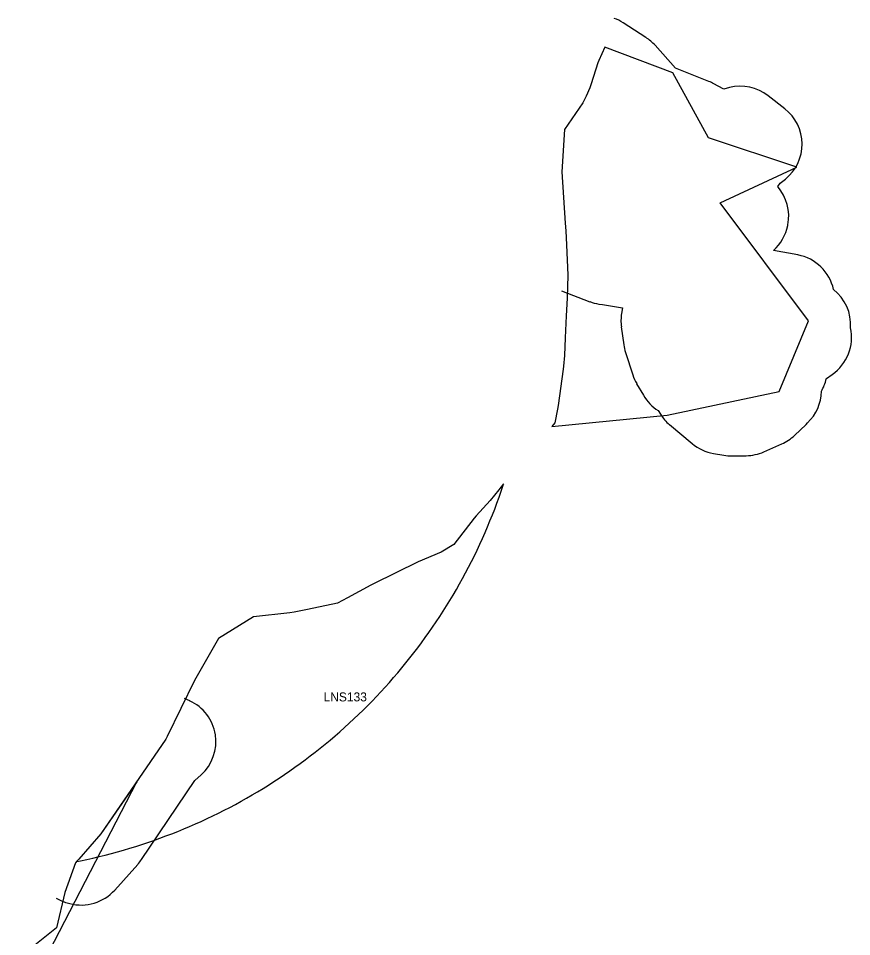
# Model space of a CAD drawing. Extents: x -546762 to -536351, y -1046851 to -1035695.
# Drawn here: x -545178 to -544249, y -1042054 to -1041031 of the extents above; entities that cross this region are included whole.
import ezdxf

# ---------------------------------------------------------------- set-up
doc = ezdxf.new("R2010")
doc.units = 0
for name, color, linetype in [('Vrstva 23', 7, 'Continuous'), ('Vrstva 24', 7, 'Continuous'), ('Vrstva 48', 7, 'Continuous')]:
    doc.layers.add(name, color=color, linetype=linetype)

msp = doc.modelspace()

# ---------------------------------------------------------------- linework, layer by layer
at = {"layer": 'Vrstva 23'}
for points in [[(-544478.4, -1041052.5), (-544503.9, -1041036)], [(-544408.3, -1041101.4), (-544445.4, -1041086.6), (-544468.3, -1041061.1)], [(-544385.3, -1041108.2), (-544391.7, -1041109.8), (-544392.4, -1041109.7), (-544402.8, -1041104)], [(-544323.7, -1041131.7), (-544342.2, -1041117.3)], [(-544331.6, -1041218.5), (-544328.7, -1041214.6), (-544323, -1041210.1)], [(-544320.4, -1041261.9), (-544320.2, -1041261)], [(-544309.2, -1041294.6), (-544336.3, -1041289.6)], [(-544572.6, -1041334.6), (-544540.9, -1041346.7)], [(-544531.1, -1041349.3), (-544526.8, -1041350), (-544504.6, -1041353.5), (-544505.7, -1041359.7)], [(-544505.9, -1041374.8), (-544503.1, -1041394.6)], [(-544501.2, -1041403.1), (-544493.1, -1041428.2)], [(-544277.5, -1041432.6), (-544277.3, -1041432.1), (-544271, -1041427.7)], [(-544488.8, -1041438), (-544481.3, -1041450.9)], [(-544464.9, -1041468), (-544462.3, -1041472)], [(-544452.1, -1041483.6), (-544426.8, -1041504.8)], [(-544312.9, -1041495.6), (-544300, -1041483.3)], [(-544300, -1041483.3), (-544298.2, -1041481.6)], [(-544347, -1041513.9), (-544327.1, -1041505.1)], [(-544403.2, -1041515.7), (-544391.6, -1041517.7)], [(-544382.7, -1041518.4), (-544366.8, -1041518.2)], [(-544987, -1041791.2), (-544992.8, -1041788.6)], [(-545040.7, -1041968.1), (-544981.1, -1041880), (-544974.2, -1041873.7)], [(-545070.5, -1042002), (-545044.9, -1041973.4)], [(-545123.7, -1042016.2), (-545120.6, -1042017)]]:
    msp.add_lwpolyline(points, dxfattribs=at)
for centre, start, end in [((-544531.1, -1041078), 57.1301, 69.7905), ((-544505.5, -1041094.5), 41.9531, 57.1301), ((-544426.8, -1041147.8), 61.2505, 68.1963), ((-544373, -1041156.7), 52.0504, 104.2278), ((-544354.4, -1041171.2), 308.8802, 52.0504), ((-544369.3, -1041251.3), 348.8112, 41.0233), ((-544369.5, -1041252.2), 311.5394, 348.8112), ((-544318.2, -1041343.8), 12.2473, 79.5739), ((-544300.2, -1041372.5), 356.4059, 51.8996), ((-544523.2, -1041299.9), 249.212, 260.8837), ((-544456.3, -1041368), 170.4755, 187.8827), ((-544299.2, -1041386.4), 304.3378, 12.4104), ((-544453.6, -1041387.8), 187.8827, 197.8307), ((-544445.5, -1041412.9), 197.8307, 210.1018), ((-544326.3, -1041421.8), 330.4344, 347.4681), ((-544438, -1041425.8), 210.1018, 237.5143), ((-544332.8, -1041445.4), 313.6678, 358.83), ((-544420.1, -1041445.3), 212.3187, 230.1188), ((-544334.5, -1041447.1), 313.6393, 313.6678), ((-544347.4, -1041459.4), 293.9544, 313.6393), ((-544394.8, -1041466.4), 230.1188, 260.3616), ((-544383.2, -1041468.4), 260.3616, 270.5762), ((-544367.3, -1041468.2), 270.5762, 293.9544), ((-545013.5, -1041834.1), 65.5109, 65.6412), ((-545007.8, -1041836.7), 312.1957, 65.5109), ((-545082.1, -1041940), 318.2032, 325.8942), ((-545107.8, -1041968.7), 255.1271, 318.2032), ((-545110.8, -1041967.9), 239.8285, 255.1271)]:
    msp.add_arc(centre, 50, start, end, dxfattribs=at)
at = {"layer": 'Vrstva 24'}
for points in [[(-544583.3, -1041485.8), (-544454.8, -1041473), (-544330, -1041446.7), (-544297.1, -1041367.9), (-544395.7, -1041236.4), (-544310.3, -1041197), (-544408.8, -1041164.2), (-544448.3, -1041091.9), (-544524.3, -1041063.1), (-544531.1, -1041078), (-544532.2, -1041080.7), (-544539.5, -1041104.2), (-544541.1, -1041108.3), (-544544.9, -1041117.7), (-544548.7, -1041125.2), (-544569.2, -1041154.9), (-544572.1, -1041201.9), (-544568.3, -1041259.2), (-544567.9, -1041267.6), (-544567, -1041283.3), (-544565.4, -1041317), (-544566.4, -1041342.6), (-544567.2, -1041362.6), (-544568.6, -1041387), (-544569.3, -1041406.7), (-544570.3, -1041418.6), (-544570.6, -1041421.8), (-544576.4, -1041462.2), (-544577, -1041466.5), (-544580, -1041481.7), (-544583.3, -1041485.8)], [(-545177.7, -1042136.7), (-545046, -1041881.4), (-545086, -1041939.5), (-545110.5, -1041967.6), (-545110.8, -1041967.9), (-545111.6, -1041968.8), (-545112.7, -1041970), (-545114.1, -1041971.7), (-545126.2, -1042004.6), (-545135.4, -1042044.2), (-545178, -1042078.1)]]:
    msp.add_lwpolyline(points, dxfattribs=at)
at = {"layer": 'Vrstva 48'}
msp.add_lwpolyline([(-545112.8, -1041970.2), (-545108.8, -1041969.4), (-545101.8, -1041967.9), (-545094.9, -1041966.4), (-545088, -1041964.7), (-545081.1, -1041963), (-545074.2, -1041961.3), (-545067.4, -1041959.4), (-545060.6, -1041957.5), (-545053.7, -1041955.5), (-545047, -1041953.4), (-545040.2, -1041951.2), (-545033.5, -1041949), (-545026.8, -1041946.7), (-545020.1, -1041944.3), (-545013.4, -1041941.8), (-545006.8, -1041939.3), (-545000.2, -1041936.7), (-544993.6, -1041934), (-544987.1, -1041931.2), (-544980.6, -1041928.4), (-544974.1, -1041925.5), (-544967.6, -1041922.5), (-544961.2, -1041919.5), (-544954.9, -1041916.4), (-544948.5, -1041913.2), (-544942.2, -1041909.9), (-544936, -1041906.6), (-544929.7, -1041903.2), (-544923.5, -1041899.7), (-544917.4, -1041896.1), (-544911.3, -1041892.5), (-544905.2, -1041888.8), (-544899.2, -1041885.1), (-544893.2, -1041881.3), (-544887.3, -1041877.4), (-544881.4, -1041873.4), (-544875.5, -1041869.4), (-544869.7, -1041865.3), (-544864, -1041861.2), (-544858.3, -1041856.9), (-544852.6, -1041852.7), (-544847, -1041848.3), (-544841.4, -1041843.9), (-544835.9, -1041839.4), (-544830.4, -1041834.9), (-544825, -1041830.3), (-544819.7, -1041825.7), (-544814.4, -1041821), (-544809.1, -1041816.2), (-544803.9, -1041811.4), (-544798.8, -1041806.5), (-544793.7, -1041801.5), (-544788.6, -1041796.5), (-544783.7, -1041791.5), (-544778.8, -1041786.3), (-544773.9, -1041781.2), (-544769.1, -1041775.9), (-544764.3, -1041770.7), (-544759.7, -1041765.3), (-544755, -1041759.9), (-544750.5, -1041754.5), (-544746, -1041749), (-544741.5, -1041743.5), (-544737.2, -1041737.9), (-544732.8, -1041732.3), (-544728.6, -1041726.6), (-544724.4, -1041720.8), (-544720.3, -1041715.1), (-544716.2, -1041709.2), (-544712.3, -1041703.4), (-544708.3, -1041697.4), (-544704.5, -1041691.5), (-544700.7, -1041685.5), (-544697, -1041679.4), (-544693.3, -1041673.4), (-544689.7, -1041667.2), (-544686.2, -1041661.1), (-544682.8, -1041654.9), (-544679.4, -1041648.6), (-544676.1, -1041642.3), (-544672.9, -1041636), (-544669.7, -1041629.7), (-544666.6, -1041623.3), (-544663.6, -1041616.8), (-544660.7, -1041610.4), (-544657.8, -1041603.9), (-544655, -1041597.4), (-544652.3, -1041590.8), (-544649.6, -1041584.2), (-544647, -1041577.6), (-544644.5, -1041571), (-544642.1, -1041564.3), (-544639.8, -1041557.6), (-544637.5, -1041550.9), (-544637.1, -1041549.7), (-544641.2, -1041554.7), (-544642.6, -1041556.4), (-544652.1, -1041568), (-544667.5, -1041585.3), (-544669.8, -1041587.9), (-544692.4, -1041617.1), (-544706.7, -1041625.8), (-544732.4, -1041636.5), (-544782.3, -1041661), (-544785, -1041662.4), (-544811.2, -1041676.4), (-544822.2, -1041682.3), (-544855.5, -1041689.7), (-544870.7, -1041692.5), (-544875.3, -1041693.3), (-544915.8, -1041697.8), (-544954.9, -1041721.8), (-544981.7, -1041768.5), (-545012, -1041830.9), (-545013.5, -1041834.1), (-545086, -1041939.5), (-545110.5, -1041967.6), (-545110.8, -1041967.9), (-545111.6, -1041968.8), (-545112.7, -1041970), (-545112.8, -1041970.2)], dxfattribs=at)

# ---------------------------------------------------------------- texts
msp.add_text('LNS133', height=10, dxfattribs=at).set_placement((-544837.8, -1041791.9))

doc.saveas('drawing.dxf')
